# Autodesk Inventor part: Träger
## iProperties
Created: 2003-12
Part Number: Träger
Material: Aluminium - 6061
Document SubType Name: Modellieren
Designer: Ulrich
Control State: 0
Master: False
Checked Out: False
Shininess: 20.0
Angle Display Precision: 2
Document Length Units: 11269
Document Angle Units: 11279
Document Time Units: 11290
Document Mass Units: 11283
Document Length Units Precision: 3
Document Angle Units Precision: 2
Density: 0.0
Volumn: 0.0
Area: 0.0
PropertySet Name: Model Information
Author: Ulrich
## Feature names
1. Grundkörper [Extrusion]
